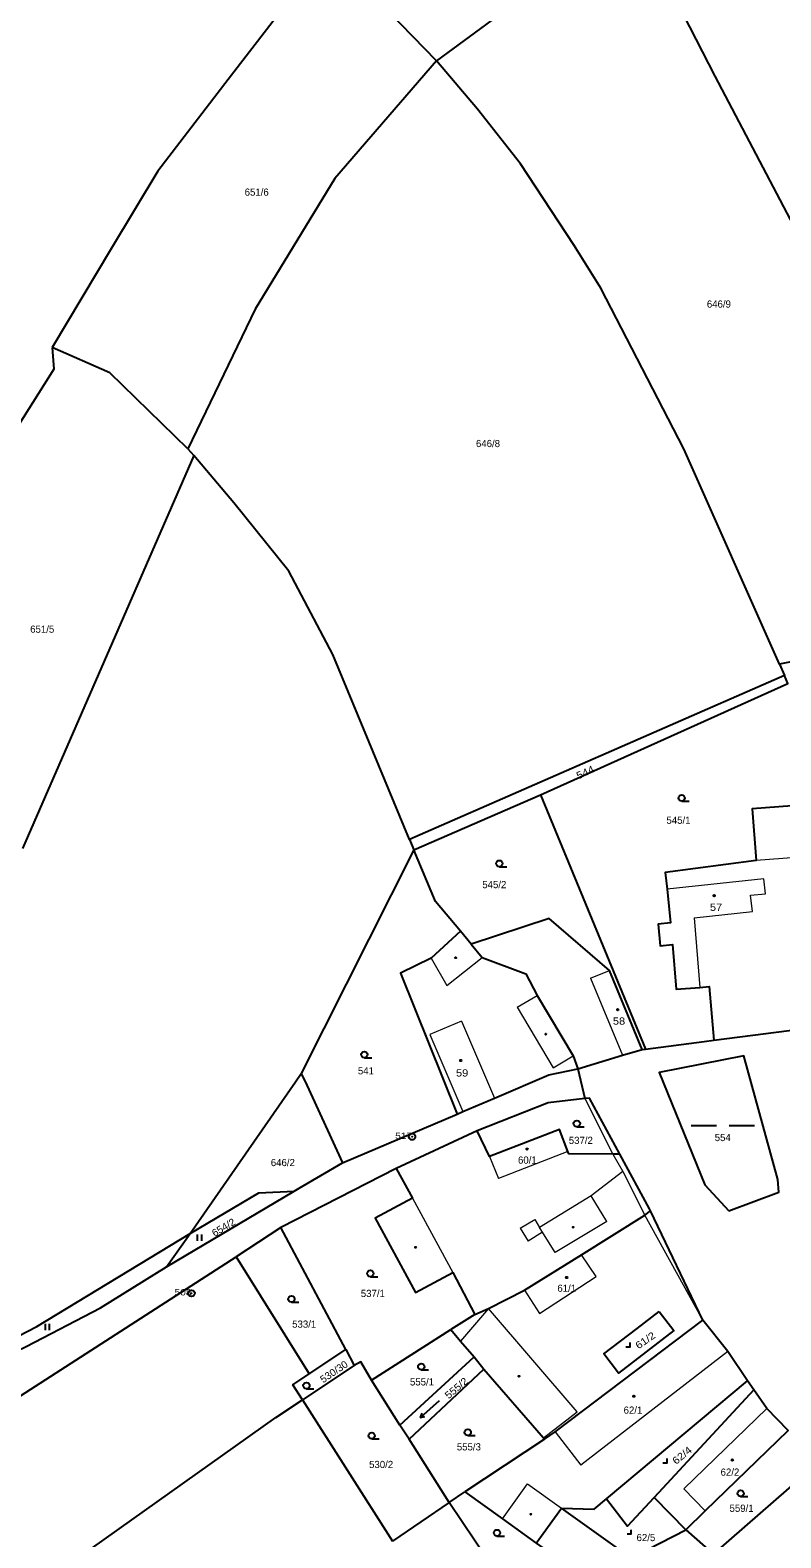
# Model space of a CAD drawing. Extents: x -687135 to -684370, y -1007309 to -1005782.
# Drawn here: x -685399.4 to -685221.9, y -1006674.4 to -1006317.9 of the extents above; entities that cross this region are included whole.
import ezdxf
from ezdxf.enums import TextEntityAlignment as Align

# ---------------------------------------------------------------- set-up
doc = ezdxf.new("R2010")
doc.units = 0
doc.header["$LTSCALE"] = 0.68
for name, color, linetype, lineweight in [('1', 7, 'Continuous', 25), ('3', 7, 'Continuous', 25), ('4', 7, 'Continuous', 13), ('5', 7, 'Continuous', 25), ('8', 7, 'Continuous', 25)]:
    doc.layers.add(name, color=color, linetype=linetype, lineweight=lineweight)
doc.layers.add('2', color=7, linetype='Continuous')

msp = doc.modelspace()

# ---------------------------------------------------------------- linework, layer by layer
at = {"layer": '1'}
for p, q in [((-685256.82, -1006291), (-685303.33, -1006325.19)), ((-685394.22, -1006392.96), (-685393.77, -1006398.11)), ((-685362.12, -1006416.9), (-685360.72, -1006418.48)), ((-685278.74, -1006498.76), (-685253.86, -1006558.86)), ((-685309.69, -1006509.25), (-685308.68, -1006511.71)), ((-685308.68, -1006511.71), (-685335.28, -1006564.59)), ((-685295.13, -1006534.02), (-685297.67, -1006530.98)), ((-685237.76, -1006556.75), (-685206.53, -1006552.66)), ((-685254.71, -1006558.9), (-685253.86, -1006558.86)), ((-685269.86, -1006563.52), (-685268.22, -1006570.53)), ((-685312.82, -1006587.03), (-685340.13, -1006601.03)), ((-685367.14, -1006610.32), (-685361.58, -1006602.4)), ((-685294.27, -1006621.56), (-685299.95, -1006625.17)), ((-685318.71, -1006637.08), (-685299.95, -1006625.17)), ((-685324.77, -1006629.84), (-685322.79, -1006633.65)), ((-685311.96, -1006647.74), (-685294.43, -1006631.61)), ((-685294.43, -1006631.61), (-685292.09, -1006634.52)), ((-685309.8, -1006651.08), (-685292.09, -1006634.52)), ((-685311.96, -1006647.74), (-685318.71, -1006637.08)), ((-685228.26, -1006639.39), (-685229.81, -1006637.3)), ((-685335.02, -1006641.79), (-685313.7, -1006675.14)), ((-685277.77, -1006651.04), (-685296.58, -1006663.55)), ((-685300.34, -1006666.05), (-685296.58, -1006663.55)), ((-685279.72, -1006675.62), (-685273.74, -1006667.38))]:
    msp.add_line(p, q, dxfattribs=at)
for points in [[(-685175.13, -1006458.36), (-685198.89, -1006402.17), (-685211.49, -1006378.14), (-685237.4, -1006328.81), (-685256.82, -1006291)], [(-685303.33, -1006325.19), (-685320.13, -1006307.86), (-685328.64, -1006298.45), (-685352.59, -1006329.63)], [(-685303.33, -1006325.19), (-685327.36, -1006352.98), (-685346.19, -1006383.9), (-685362.12, -1006416.9)], [(-685222.19, -1006467.84), (-685244.84, -1006416.91), (-685264.46, -1006378.96), (-685270.8, -1006368.81), (-685283.47, -1006349.5), (-685293.62, -1006336.58), (-685303.33, -1006325.19)], [(-685352.59, -1006329.63), (-685369.22, -1006351.28), (-685380.12, -1006369.46), (-685394.22, -1006392.96)], [(-685362.12, -1006416.9), (-685380.57, -1006398.91), (-685394.22, -1006392.96)], [(-685393.77, -1006398.11), (-685416.6, -1006434.12), (-685436.19, -1006473.76)], [(-685309.69, -1006509.25), (-685327.83, -1006465.55), (-685338.19, -1006445.81), (-685351.21, -1006429.71), (-685360.72, -1006418.48), (-685401.24, -1006511.39)], [(-685175.13, -1006458.36), (-685222.19, -1006467.84), (-685221, -1006470.47)], [(-685297.67, -1006530.98), (-685303.55, -1006523.96), (-685308.68, -1006511.71), (-685278.74, -1006498.76), (-685220.24, -1006472.43), (-685221, -1006470.47), (-685309.69, -1006509.25)], [(-685208.75, -1006500.55), (-685228.69, -1006502.07), (-685227.76, -1006514.23), (-685249.22, -1006517.08), (-685248.8, -1006521.04), (-685247.95, -1006529), (-685250.93, -1006529.31), (-685250.4, -1006534.39), (-685247.53, -1006534.08), (-685246.66, -1006544.7), (-685241.08, -1006544.24), (-685238.81, -1006544.06), (-685237.76, -1006556.75)], [(-685254.71, -1006558.9), (-685262.43, -1006540.23), (-685276.66, -1006527.94), (-685295.13, -1006534.02)], [(-685297.67, -1006530.98), (-685304.57, -1006537.31), (-685311.84, -1006540.89), (-685298.44, -1006574.19)], [(-685295.13, -1006534.02), (-685292.5, -1006537.15), (-685282.19, -1006541.05), (-685279.51, -1006546.14), (-685270.97, -1006560.46), (-685269.86, -1006563.52)], [(-685253.86, -1006558.86), (-685240.02, -1006557.05), (-685237.76, -1006556.75)], [(-685269.86, -1006563.52), (-685259.37, -1006560.27), (-685254.71, -1006558.9)], [(-685298.44, -1006574.19), (-685297.1, -1006573.62), (-685289.61, -1006570.42), (-685276.74, -1006564.93), (-685269.86, -1006563.52)], [(-685361.58, -1006602.4), (-685336.68, -1006566.6), (-685335.28, -1006564.59)], [(-685335.28, -1006564.59), (-685333.99, -1006567.39), (-685325.55, -1006585.75), (-685298.44, -1006574.19)], [(-685268.22, -1006570.53), (-685276.92, -1006571.55), (-685293.72, -1006578.16)], [(-685259.98, -1006583.67), (-685267.17, -1006570.41), (-685268.22, -1006570.53)], [(-685259.98, -1006583.67), (-685261.6, -1006583.66), (-685272.03, -1006583.57), (-685272.24, -1006583.02), (-685274.26, -1006577.84), (-685290.81, -1006584.25), (-685293.72, -1006578.16), (-685312.82, -1006587.03)], [(-685252.74, -1006597.07), (-685252.97, -1006596.59), (-685259.98, -1006583.67)], [(-685336.98, -1006592.43), (-685335.8, -1006591.74), (-685325.55, -1006585.75)], [(-685312.82, -1006587.03), (-685309.01, -1006594.06), (-685317.79, -1006598.83), (-685308.26, -1006616.41), (-685299.47, -1006611.64), (-685294.27, -1006621.56)], [(-685461.51, -1006651.87), (-685441.02, -1006648.66), (-685400.31, -1006629.14), (-685382.75, -1006620.03), (-685367.14, -1006610.32), (-685336.98, -1006592.43)], [(-685361.58, -1006602.4), (-685345.3, -1006592.78), (-685336.98, -1006592.43)], [(-685294.27, -1006621.56), (-685291.05, -1006620.15), (-685282.54, -1006615.87), (-685269, -1006607.5), (-685254.03, -1006598.1), (-685252.74, -1006597.07)], [(-685292.09, -1006634.52), (-685278.05, -1006650.72), (-685277.77, -1006651.04), (-685275.22, -1006649.33), (-685240.36, -1006622.9), (-685252.74, -1006597.07)], [(-685461.13, -1006650.6), (-685460.84, -1006649.6), (-685441.89, -1006647.2), (-685397.85, -1006624.39), (-685361.58, -1006602.4)], [(-685437.58, -1006657.94), (-685408.86, -1006645.35), (-685350.72, -1006607.99)], [(-685273.74, -1006667.38), (-685266.04, -1006667.57), (-685263.14, -1006665.15), (-685229.81, -1006637.3), (-685234.45, -1006630.36), (-685240.36, -1006622.9)], [(-685299.95, -1006625.17), (-685297.61, -1006627.9), (-685294.43, -1006631.61)], [(-685318.71, -1006637.08), (-685321.19, -1006632.74), (-685322.79, -1006633.65), (-685335.02, -1006641.79)], [(-685335.02, -1006641.79), (-685337.3, -1006638.22), (-685333.45, -1006635.6)], [(-685413.15, -1006696.73), (-685384.89, -1006676.88), (-685341.29, -1006645.97), (-685335.02, -1006641.79)], [(-685228.26, -1006639.39), (-685251.86, -1006664.83), (-685244.38, -1006672.48)], [(-685244.38, -1006672.48), (-685239.79, -1006668.03), (-685220.18, -1006649.03), (-685225.21, -1006643.84), (-685228.26, -1006639.39)], [(-685300.34, -1006666.05), (-685309.8, -1006651.08), (-685311.96, -1006647.74)], [(-685244.38, -1006672.48), (-685237.81, -1006678.26), (-685212.49, -1006656.18)], [(-685296.58, -1006663.55), (-685287.7, -1006669.89), (-685279.72, -1006675.62)], [(-685280.06, -1006701.85), (-685283.18, -1006692.03), (-685288.04, -1006684.34), (-685300.34, -1006666.05), (-685313.7, -1006675.14)], [(-685263.14, -1006665.15), (-685258.18, -1006671.64), (-685251.86, -1006664.83)], [(-685279.72, -1006675.62), (-685264.15, -1006686.64), (-685258.28, -1006678.42), (-685273.74, -1006667.38)], [(-685255.62, -1006680.32), (-685255.04, -1006679.45), (-685253.41, -1006677.18), (-685244.38, -1006672.48)]]:
    msp.add_lwpolyline(points, dxfattribs=at)
for points in [[(-685234.17, -1006597.09), (-685222.37, -1006592.66), (-685222.58, -1006589.65), (-685230.67, -1006560.45), (-685250.66, -1006564.36), (-685239.88, -1006590.96)], [(-685333.45, -1006635.6), (-685324.77, -1006629.84), (-685340.13, -1006601.03), (-685350.72, -1006607.99)], [(-685250.66, -1006620.88), (-685247.23, -1006625.37), (-685260.29, -1006635.45), (-685263.76, -1006630.92), (-685255.9, -1006624.9)]]:
    msp.add_lwpolyline(points, close=True, dxfattribs=at)
at = {"layer": '3'}
for p, q in [((-685245.343, -1006500.23), (-685243.593, -1006500.23)), ((-685288.443, -1006515.71), (-685286.693, -1006515.71)), ((-685320.363, -1006560.9), (-685318.613, -1006560.9)), ((-685270.133, -1006577.2), (-685268.383, -1006577.2)), ((-685243.139, -1006576.92), (-685237.139, -1006576.92)), ((-685234.139, -1006576.92), (-685228.139, -1006576.92)), ((-685359.801, -1006604.19), (-685359.801, -1006602.69)), ((-685358.8, -1006604.19), (-685358.8, -1006602.69)), ((-685318.943, -1006612.64), (-685317.193, -1006612.64)), ((-685337.603, -1006618.68), (-685335.853, -1006618.68)), ((-685395.791, -1006625.31), (-685395.791, -1006623.81)), ((-685394.79, -1006625.31), (-685394.79, -1006623.81)), ((-685306.923, -1006634.67), (-685305.173, -1006634.67)), ((-685334.053, -1006639.15), (-685332.303, -1006639.15)), ((-685307.128, -1006645.972), (-685306.737, -1006644.946)), ((-685318.643, -1006651), (-685316.893, -1006651)), ((-685295.913, -1006650.2), (-685294.163, -1006650.2)), ((-685231.413, -1006664.62), (-685229.663, -1006664.62)), ((-685289.013, -1006673.97), (-685287.263, -1006673.97))]:
    msp.add_line(p, q, dxfattribs=at)
for points in [[(-685258.541, -1006629.2), (-685257.54, -1006629.2), (-685257.54, -1006628.2)], [(-685302.669, -1006641.958), (-685307.128, -1006645.972), (-685306.066, -1006645.691)], [(-685249.781, -1006656.66), (-685248.78, -1006656.66), (-685248.78, -1006655.66)], [(-685258.271, -1006673.46), (-685257.27, -1006673.46), (-685257.27, -1006672.46)]]:
    msp.add_lwpolyline(points, dxfattribs=at)
for centre in [(-685245.3429, -1006499.4798), (-685288.4429, -1006514.9598), (-685320.3629, -1006560.1498), (-685270.1329, -1006576.4498), (-685318.9429, -1006611.8898), (-685337.6029, -1006617.9298), (-685306.9229, -1006633.9198), (-685334.0529, -1006638.3998), (-685295.9129, -1006649.4498), (-685318.6429, -1006650.2498), (-685231.4129, -1006663.8698), (-685289.0129, -1006673.2198)]:
    msp.add_circle(centre, 0.75, dxfattribs=at)
at = {"layer": '4'}
for p, q in [((-685207.82, -1006512.71), (-685227.76, -1006514.23)), ((-685225.92, -1006518.62), (-685248.8, -1006521.04)), ((-685242.41, -1006527.79), (-685241.08, -1006544.24)), ((-685304.57, -1006537.31), (-685300.88, -1006543.81)), ((-685300.88, -1006543.81), (-685292.5, -1006537.15)), ((-685266.9, -1006542.09), (-685262.43, -1006540.23)), ((-685266.9, -1006542.09), (-685259.37, -1006560.27)), ((-685284.24, -1006548.96), (-685279.51, -1006546.14)), ((-685284.24, -1006548.96), (-685275.7, -1006563.28)), ((-685297.38, -1006552.21), (-685304.87, -1006555.4)), ((-685297.38, -1006552.21), (-685289.61, -1006570.42)), ((-685304.87, -1006555.4), (-685297.1, -1006573.62)), ((-685275.7, -1006563.28), (-685270.97, -1006560.46)), ((-685268.22, -1006570.53), (-685261.6, -1006583.66)), ((-685290.81, -1006584.25), (-685288.68, -1006589.43)), ((-685272.24, -1006583.02), (-685288.68, -1006589.43)), ((-685261.6, -1006583.66), (-685259.27, -1006587.76)), ((-685259.27, -1006587.76), (-685266.71, -1006593.52)), ((-685259.27, -1006587.76), (-685254.03, -1006598.1)), ((-685309.01, -1006594.06), (-685299.47, -1006611.64)), ((-685266.71, -1006593.52), (-685278.94, -1006601.02)), ((-685263.01, -1006599.61), (-685266.71, -1006593.52)), ((-685283.5, -1006601.2), (-685280.1, -1006599.12)), ((-685280.1, -1006599.12), (-685278.94, -1006601.02)), ((-685240.36, -1006622.9), (-685254.03, -1006598.1)), ((-685283.5, -1006601.2), (-685281.65, -1006604.22)), ((-685278.25, -1006602.14), (-685281.65, -1006604.22)), ((-685263.01, -1006599.61), (-685275.29, -1006606.96)), ((-685265.58, -1006612.57), (-685269, -1006607.5)), ((-685278.93, -1006621.33), (-685265.58, -1006612.57)), ((-685282.54, -1006615.87), (-685278.93, -1006621.33)), ((-685234.45, -1006630.36), (-685269.18, -1006657.24)), ((-685278.05, -1006650.72), (-685270.02, -1006644.63)), ((-685244.82, -1006662.84), (-685225.21, -1006643.84)), ((-685275.22, -1006649.33), (-685269.18, -1006657.24)), ((-685287.7, -1006669.89), (-685281.8, -1006661.62)), ((-685281.8, -1006661.62), (-685273.74, -1006667.38)), ((-685239.79, -1006668.03), (-685244.82, -1006662.84))]:
    msp.add_line(p, q, dxfattribs=at)
for points in [[(-685229.04, -1006522.47), (-685225.56, -1006522.09), (-685225.92, -1006518.62)], [(-685242.41, -1006527.79), (-685228.63, -1006526.32), (-685229.04, -1006522.47)], [(-685275.29, -1006606.96), (-685278.25, -1006602.14), (-685278.94, -1006601.02)], [(-685270.02, -1006644.63), (-685291.05, -1006620.15), (-685297.61, -1006627.9)]]:
    msp.add_lwpolyline(points, dxfattribs=at)
at = {"layer": '5'}
for centre, radius in [((-685237.6568, -1006522.5692), 0.175), ((-685298.7848, -1006537.2394), 0.1225), ((-685260.4468, -1006549.5092), 0.175), ((-685277.4448, -1006555.3094), 0.1225), ((-685297.5768, -1006561.5292), 0.175), ((-685281.8868, -1006582.4792), 0.175), ((-685270.9748, -1006600.9494), 0.1225), ((-685308.2548, -1006605.7094), 0.1225), ((-685272.5368, -1006612.8392), 0.175), ((-685283.8148, -1006636.1794), 0.1225), ((-685256.6568, -1006640.8992), 0.175), ((-685233.3768, -1006655.9792), 0.175), ((-685281.0048, -1006668.8094), 0.1225)]:
    msp.add_circle(centre, radius, dxfattribs=at)
at = {"layer": '8'}
for centre, radius in [((-685309.07, -1006579.5598), 0.75), ((-685309.07, -1006579.5598), 0.03), ((-685361.23, -1006616.5798), 0.75), ((-685361.23, -1006616.5798), 0.03)]:
    msp.add_circle(centre, radius, dxfattribs=at)

# ---------------------------------------------------------------- texts
at = {"layer": '2'}
for s, p in [('651/6', (-685348.67, -1006357.07)), ('646/9', (-685239.39, -1006383.53)), ('646/8', (-685293.98, -1006416.51)), ('651/5', (-685399.38, -1006460.4)), ('545/1', (-685248.94, -1006505.57)), ('545/2', (-685292.49, -1006520.789)), ('541', (-685321.9, -1006564.809)), ('537/2', (-685272.03, -1006581.26)), ('554', (-685237.53, -1006580.59)), ('646/2', (-685342.49, -1006586.51)), ('60/1', (-685284.04, -1006585.919)), ('537/1', (-685321.21, -1006617.45)), ('61/1', (-685274.73, -1006616.22)), ('533/1', (-685337.44, -1006624.71)), ('555/1', (-685309.59, -1006638.36)), ('62/1', (-685259.07, -1006645.039)), ('555/3', (-685298.5, -1006653.72)), ('530/2', (-685319.25, -1006657.89)), ('62/2', (-685236.14, -1006659.7)), ('559/1', (-685234.02, -1006668.24)), ('62/5', (-685256.01, -1006675.169))]:
    msp.add_text(s, height=1.7, dxfattribs=at).set_placement(p)
for s, rotation, width, p in [('544', 25, 1.15, (-685269.76, -1006495.09)), ('654/2', 31, 1.05, (-685355.782, -1006603.248)), ('61/2', 35, 1.15, (-685255.542, -1006629.856)), ('530/30', 34, 1.05, (-685330.124, -1006637.854)), ('555/2', 40, 1.1, (-685300.463, -1006641.651)), ('62/4', 39, 1.15, (-685246.695, -1006657.15))]:
    msp.add_text(s, height=1.7, rotation=rotation, dxfattribs=dict(at, width=width)).set_placement(p)
at = {"layer": '2', "width": 1.15}
for s, p in [('57', (-685238.67, -1006526.15)), ('58', (-685261.61, -1006553.059)), ('59', (-685298.71, -1006565.32))]:
    msp.add_text(s, height=1.7, dxfattribs=at).set_placement(p)
at = {"layer": '8', "width": 1.2}
for s, p in [('517', (-685309.07, -1006580.06)), ('508', (-685361.23, -1006617.08))]:
    msp.add_text(s, height=1.5, dxfattribs=at).set_placement(p, align=Align.RIGHT)

doc.saveas('drawing.dxf')
